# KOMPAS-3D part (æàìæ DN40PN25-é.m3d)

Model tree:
1. Объединить компоненты:1  (labels: СЕНС DN40PN25-В)

Referenced files in D:\Савин\!СЕНСОР\3D для заказчика\!Новый перечень\СЕНС\3. СЕНС-В\DN40\: СЕНС DN40PN25-В.a3d
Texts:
  СЕНС DN40PN25-В
  ООО НПП Сенсор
